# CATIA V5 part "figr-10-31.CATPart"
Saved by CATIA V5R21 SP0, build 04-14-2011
Part number: Part1
Bounding box of the stored display mesh (mm): x -85.282 to 128.744, y -7.97 to 191.596, z 0 to 148.964
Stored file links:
  D:\CATIA V5R21 E-RESOURCES\CATIA-V5R21\catia-v5r21-prt\c10-catia-v5r20-prt\c10-catia-v5r21-figr-10-31.CATPart
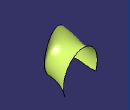
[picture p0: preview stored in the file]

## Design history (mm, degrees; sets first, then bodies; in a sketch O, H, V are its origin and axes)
Set1
  Sketch1 on xy-plane, origin (0, 0, 0), H (1, 0, 0), V (0, 1, 0)
    spline S1 through (-60, 0) (-70, 70) (-70, 170) (-80, 190)
  Sketch2 on yz-plane, origin (0, 0, 0), H (0, 1, 0), V (0, 0, 1)
    spline S1 through (0, 170) (100, 120) (180, 150)
  Sketch3 on xy-plane, origin (0, 0, 0), H (1, 0, 0), V (0, 1, 0)
    spline S1 through (70, 0) (70, 80) (120, 190)
  Sweep1: type Circle, Guide (Sketch1; Sketch2; Sketch3)
Body1 (main body)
